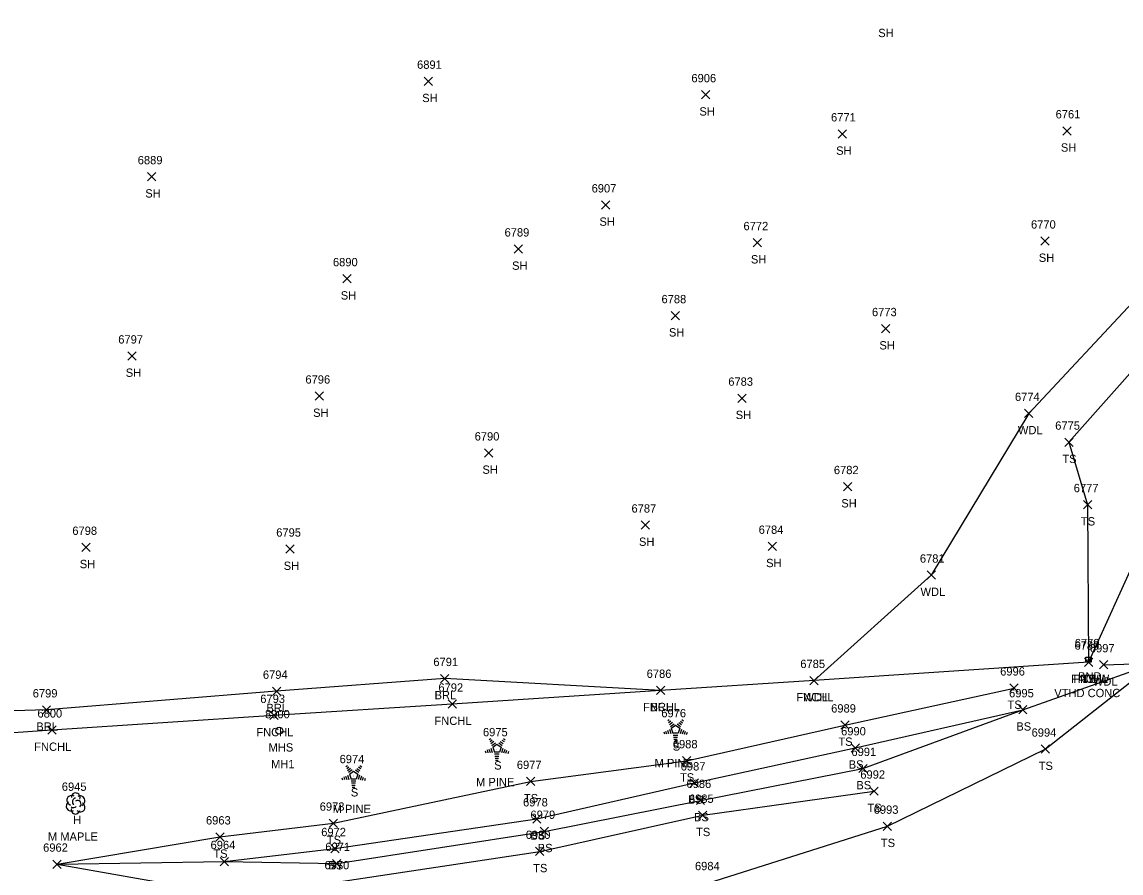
# Model space of a CAD drawing. Extents: x 1678863 to 1683592, y 407783 to 418211.
# Drawn here: x 1680572.7 to 1680837, y 408997.5 to 409202.1 of the extents above; entities that cross this region are included whole.
import ezdxf

# ---------------------------------------------------------------- set-up
doc = ezdxf.new("R2010")
doc.units = 0
for name, color, linetype in [('L_A', 7, 'Continuous'), ('L_C', 7, 'Continuous'), ('L_I', 7, 'Continuous'), ('L_TIC', 7, 'Continuous'), ('LABL', 7, 'Continuous'), ('LAWA', 7, 'Continuous'), ('LELB', 7, 'Continuous'), ('Level 18', 7, 'Continuous'), ('LFNC', 7, 'Continuous'), ('LTC', 7, 'Continuous'), ('LTD', 7, 'Continuous'), ('M_A', 7, 'Continuous'), ('M_C', 7, 'Continuous'), ('M_I', 7, 'Continuous'), ('U_A', 7, 'Continuous'), ('U_C', 7, 'Continuous'), ('U_I', 7, 'Continuous'), ('USMH', 7, 'Continuous')]:
    doc.layers.add(name, color=color, linetype=linetype)

msp = doc.modelspace()

# ---------------------------------------------------------------- linework, layer by layer
at = {"layer": 'L_TIC'}
for points in [[(1680669.47, 409186.88), (1680671.47, 409188.88)], [(1680671.47, 409186.88), (1680669.47, 409188.88)], [(1680736.15, 409183.64), (1680738.15, 409185.64)], [(1680738.15, 409183.64), (1680736.15, 409185.64)], [(1680823.09, 409174.96), (1680825.09, 409176.96)], [(1680825.09, 409174.96), (1680823.09, 409176.96)], [(1680769.04, 409174.22), (1680771.04, 409176.22)], [(1680771.04, 409174.22), (1680769.04, 409176.22)], [(1680602.86, 409163.93), (1680604.86, 409165.93)], [(1680604.86, 409163.93), (1680602.86, 409165.93)], [(1680712.1, 409157.15), (1680714.1, 409159.15)], [(1680714.1, 409157.15), (1680712.1, 409159.15)], [(1680691.08, 409146.56), (1680693.08, 409148.56)], [(1680693.08, 409146.56), (1680691.08, 409148.56)], [(1680748.55, 409148.08), (1680750.55, 409150.08)], [(1680750.55, 409148.08), (1680748.55, 409150.08)], [(1680817.79, 409148.47), (1680819.79, 409150.47)], [(1680819.79, 409148.47), (1680817.79, 409150.47)], [(1680649.88, 409139.41), (1680651.88, 409141.41)], [(1680651.88, 409139.41), (1680649.88, 409141.41)], [(1680728.82, 409130.52), (1680730.82, 409132.52)], [(1680730.82, 409130.52), (1680728.82, 409132.52)], [(1680779.44, 409127.41), (1680781.44, 409129.41)], [(1680781.44, 409127.41), (1680779.44, 409129.41)], [(1680598.16, 409120.83), (1680600.16, 409122.83)], [(1680600.16, 409120.83), (1680598.16, 409122.83)], [(1680643.23, 409111.2), (1680645.23, 409113.2)], [(1680645.23, 409111.2), (1680643.23, 409113.2)], [(1680744.89, 409110.68), (1680746.89, 409112.68)], [(1680746.89, 409110.68), (1680744.89, 409112.68)], [(1680813.84, 409107.02), (1680815.84, 409109.02)], [(1680815.84, 409107.02), (1680813.84, 409109.02)], [(1680823.53, 409100.11), (1680825.53, 409102.11)], [(1680825.53, 409100.11), (1680823.53, 409102.11)], [(1680683.96, 409097.52), (1680685.96, 409099.52)], [(1680685.96, 409097.52), (1680683.96, 409099.52)], [(1680770.28, 409089.43), (1680772.28, 409091.43)], [(1680772.28, 409089.43), (1680770.28, 409091.43)], [(1680827.99, 409085.09), (1680829.99, 409087.09)], [(1680829.99, 409085.09), (1680827.99, 409087.09)], [(1680721.61, 409080.19), (1680723.61, 409082.19)], [(1680723.61, 409080.19), (1680721.61, 409082.19)], [(1680587.1, 409074.83), (1680589.1, 409076.83)], [(1680589.1, 409074.83), (1680587.1, 409076.83)], [(1680752.2, 409075.08), (1680754.2, 409077.08)], [(1680754.2, 409075.08), (1680752.2, 409077.08)], [(1680636.15, 409074.41), (1680638.15, 409076.41)], [(1680638.15, 409074.41), (1680636.15, 409076.41)], [(1680790.41, 409068.15), (1680792.41, 409070.15)], [(1680792.41, 409068.15), (1680790.41, 409070.15)], [(1680828.25, 409047.23), (1680830.25, 409049.23)], [(1680830.25, 409047.23), (1680828.25, 409049.23)], [(1680828.25, 409047.23), (1680830.25, 409049.23)], [(1680830.25, 409047.23), (1680828.25, 409049.23)], [(1680828.25, 409047.23), (1680830.25, 409049.23)], [(1680830.25, 409047.23), (1680828.25, 409049.23)], [(1680831.86, 409046.6), (1680833.86, 409048.6)], [(1680833.86, 409046.6), (1680831.86, 409048.6)], [(1680673.38, 409043.29), (1680675.38, 409045.29)], [(1680675.38, 409043.29), (1680673.38, 409045.29)], [(1680762.22, 409042.82), (1680764.22, 409044.82)], [(1680764.22, 409042.82), (1680762.22, 409044.82)], [(1680762.22, 409042.82), (1680764.22, 409044.82)], [(1680764.22, 409042.82), (1680762.22, 409044.82)], [(1680632.95, 409040.23), (1680634.95, 409042.23)], [(1680634.95, 409040.23), (1680632.95, 409042.23)], [(1680725.31, 409040.45), (1680727.31, 409042.45)], [(1680727.31, 409040.45), (1680725.31, 409042.45)], [(1680725.31, 409040.45), (1680727.31, 409042.45)], [(1680727.31, 409040.45), (1680725.31, 409042.45)], [(1680810.34, 409041.01), (1680812.34, 409043.01)], [(1680812.34, 409041.01), (1680810.34, 409043.01)], [(1680577.59, 409035.75), (1680579.59, 409037.75)], [(1680579.59, 409035.75), (1680577.59, 409037.75)], [(1680675.17, 409037.14), (1680677.17, 409039.14)], [(1680677.17, 409037.14), (1680675.17, 409039.14)], [(1680812.43, 409035.78), (1680814.43, 409037.78)], [(1680814.43, 409035.78), (1680812.43, 409037.78)], [(1680812.43, 409035.78), (1680814.43, 409037.78)], [(1680814.43, 409035.78), (1680812.43, 409037.78)], [(1680632.31, 409034.42), (1680634.31, 409036.42)], [(1680634.31, 409034.42), (1680632.31, 409036.42)], [(1680578.88, 409030.91), (1680580.88, 409032.91)], [(1680580.88, 409030.91), (1680578.88, 409032.91)], [(1680769.65, 409032.12), (1680771.65, 409034.12)], [(1680771.65, 409032.12), (1680769.65, 409034.12)], [(1680772.11, 409026.63), (1680774.11, 409028.63)], [(1680774.11, 409026.63), (1680772.11, 409028.63)], [(1680817.84, 409026.32), (1680819.84, 409028.32)], [(1680819.84, 409026.32), (1680817.84, 409028.32)], [(1680731.55, 409023.53), (1680733.55, 409025.53)], [(1680733.55, 409023.53), (1680731.55, 409025.53)], [(1680773.95, 409021.67), (1680775.95, 409023.67)], [(1680775.95, 409021.67), (1680773.95, 409023.67)], [(1680694.02, 409018.55), (1680696.02, 409020.55)], [(1680696.02, 409018.55), (1680694.02, 409020.55)], [(1680733.45, 409018.19), (1680735.45, 409020.19)], [(1680735.45, 409018.19), (1680733.45, 409020.19)], [(1680734.9, 409013.98), (1680736.9, 409015.98)], [(1680736.9, 409013.98), (1680734.9, 409015.98)], [(1680776.65, 409016.22), (1680778.65, 409018.22)], [(1680778.65, 409016.22), (1680776.65, 409018.22)], [(1680646.61, 409008.52), (1680648.61, 409010.52)], [(1680648.61, 409008.52), (1680646.61, 409010.52)], [(1680695.53, 409009.55), (1680697.53, 409011.55)], [(1680697.53, 409009.55), (1680695.53, 409011.55)], [(1680735.42, 409010.41), (1680737.42, 409012.41)], [(1680737.42, 409010.41), (1680735.42, 409012.41)], [(1680697.31, 409006.55), (1680699.31, 409008.55)], [(1680699.31, 409006.55), (1680697.31, 409008.55)], [(1680779.87, 409007.78), (1680781.87, 409009.78)], [(1680781.87, 409007.78), (1680779.87, 409009.78)], [(1680619.3, 409005.21), (1680621.3, 409007.21)], [(1680621.3, 409005.21), (1680619.3, 409007.21)], [(1680646.98, 409002.4), (1680648.98, 409004.4)], [(1680648.98, 409002.4), (1680646.98, 409004.4)], [(1680696.24, 409001.73), (1680698.24, 409003.73)], [(1680698.24, 409001.73), (1680696.24, 409003.73)], [(1680580.13, 408998.66), (1680582.13, 409000.66)], [(1680582.13, 408998.66), (1680580.13, 409000.66)], [(1680580.13, 408998.66), (1680582.13, 409000.66)], [(1680582.13, 408998.66), (1680580.13, 409000.66)], [(1680580.13, 408998.66), (1680582.13, 409000.66)], [(1680582.13, 408998.66), (1680580.13, 409000.66)], [(1680620.4, 408999.29), (1680622.4, 409001.29)], [(1680622.4, 408999.29), (1680620.4, 409001.29)], [(1680620.4, 408999.29), (1680622.4, 409001.29)], [(1680622.4, 408999.29), (1680620.4, 409001.29)], [(1680647.39, 408998.82), (1680649.39, 409000.82)], [(1680649.39, 408998.82), (1680647.39, 409000.82)]]:
    msp.add_lwpolyline(points, dxfattribs=at)
at = {"layer": 'LABL'}
msp.add_lwpolyline([(1680726.31, 409041.45), (1680674.38, 409044.29), (1680633.95, 409041.23), (1680578.59, 409036.75), (1680531.3, 409035.36), (1680498.96, 409035.63)], dxfattribs=at)
at = {"layer": 'LAWA'}
for points in [[(1680896.75, 409201.77), (1680859.26, 409167.08), (1680840.94, 409135.88), (1680814.84, 409108.02), (1680791.41, 409069.15), (1680763.22, 409043.82)], [(1680832.86, 409047.6), (1680845.07, 409047.96), (1680857.13, 409068.65), (1680880.59, 409112.63), (1680897.26, 409128.4), (1680910.16, 409137.35), (1680926.51, 409159.25), (1680914.95, 409173.01)]]:
    msp.add_lwpolyline(points, dxfattribs=at)
at = {"layer": 'LELB'}
for points in [[(1680883.78, 409168.4), (1680867.18, 409158.31), (1680851.39, 409131.33), (1680824.53, 409101.11), (1680828.99, 409086.09), (1680829.25, 409048.23)], [(1680581.13, 408999.66), (1680621.4, 409000.29), (1680647.98, 409003.4), (1680696.53, 409010.55), (1680734.45, 409019.19), (1680773.11, 409027.63), (1680813.43, 409036.78), (1680845.07, 409047.96)], [(1680622.09, 408948.51), (1680651.12, 408965.11), (1680694.79, 408980.06), (1680737.87, 408995.22), (1680780.87, 409008.78), (1680818.84, 409027.32), (1680845.07, 409047.96)], [(1680581.13, 408999.66), (1680620.3, 409006.21), (1680647.61, 409009.52), (1680695.02, 409019.55), (1680732.55, 409024.53), (1680770.65, 409033.12), (1680811.34, 409042.01)], [(1680621.4, 409000.29), (1680648.39, 408999.82), (1680698.31, 409007.55), (1680735.9, 409014.98), (1680774.95, 409022.67), (1680813.43, 409036.78)], [(1680581.13, 408999.66), (1680622.52, 408992.36), (1680648.86, 408995.44), (1680697.24, 409002.73), (1680736.42, 409011.41), (1680777.65, 409017.22)]]:
    msp.add_lwpolyline(points, dxfattribs=at)
at = {"layer": 'Level 18'}
msp.add_lwpolyline([(1680828.6, 409049.45), (1680829.85, 409049.45), (1680829.85, 409048.2), (1680828.6, 409048.2)], close=True, dxfattribs=at)
msp.add_circle((1680829.22, 409048.82), 0.0833, dxfattribs=at)
at = {"layer": 'LFNC'}
for points in [[(1681020.97, 409571.46), (1681000.88, 409509.71), (1680983.07, 409456.41), (1680966.99, 409407.97), (1680949.18, 409354.43), (1680932.44, 409305.73), (1680912.74, 409247.22), (1680896.75, 409201.77), (1680883.78, 409168.4), (1680880.32, 409157.8), (1680862.92, 409120.89), (1680841.17, 409074.48), (1680829.25, 409048.23)], [(1680829.25, 409048.23), (1680763.22, 409043.82), (1680726.31, 409041.45), (1680676.17, 409038.14), (1680633.31, 409035.42), (1680579.88, 409031.91), (1680532.48, 409028.57), (1680500, 409026.54), (1680429.19, 409022.26), (1680381.9, 409017.89)]]:
    msp.add_lwpolyline(points, dxfattribs=at)
at = {"layer": 'LTC'}
for p, q in [((1680728.03, 409034.19), (1680728.38, 409034.44)), ((1680731.42, 409034.43), (1680731.84, 409034.12)), ((1680727.51, 409031.68), (1680727.73, 409031.03)), ((1680727.97, 409031.9), (1680728.24, 409031.06)), ((1680728.24, 409033.72), (1680728.76, 409034.1)), ((1680728.42, 409032.11), (1680728.76, 409031.09)), ((1680728.45, 409033.25), (1680729.15, 409033.77)), ((1680728.65, 409032.79), (1680729.53, 409033.43)), ((1680728.88, 409032.33), (1680729.89, 409033.07)), ((1680728.88, 409032.33), (1680729.27, 409031.14)), ((1680729.89, 409033.07), (1680730.89, 409032.34)), ((1680730.31, 409033.38), (1680731.12, 409032.79)), ((1680730.89, 409032.34), (1680730.5, 409031.14)), ((1680730.68, 409033.73), (1680731.36, 409033.24)), ((1680731.33, 409032.07), (1680730.99, 409031.03)), ((1680731.05, 409034.08), (1680731.6, 409033.68)), ((1680731.77, 409031.82), (1680731.48, 409030.94)), ((1680732.21, 409031.57), (1680731.98, 409030.84)), ((1680685.08, 409029.63), (1680685.43, 409029.88)), ((1680685.29, 409029.16), (1680685.82, 409029.54)), ((1680685.5, 409028.69), (1680686.2, 409029.21)), ((1680687.73, 409029.17), (1680688.41, 409028.68)), ((1680688.1, 409029.52), (1680688.65, 409029.12)), ((1680688.48, 409029.87), (1680688.89, 409029.56)), ((1680727.06, 409031.46), (1680727.21, 409031)), ((1680730.5, 409031.14), (1680729.27, 409031.14)), ((1680730.46, 409030.64), (1680729.31, 409030.64)), ((1680730.37, 409030.14), (1680729.39, 409030.14)), ((1680730.29, 409029.64), (1680729.46, 409029.64)), ((1680730.21, 409029.14), (1680729.53, 409029.14)), ((1680732.66, 409031.32), (1680732.47, 409030.75)), ((1680684.11, 409026.9), (1680684.26, 409026.44)), ((1680684.56, 409027.12), (1680684.78, 409026.47)), ((1680685.02, 409027.34), (1680685.29, 409026.5)), ((1680685.48, 409027.55), (1680685.81, 409026.54)), ((1680685.71, 409028.23), (1680686.58, 409028.87)), ((1680685.93, 409027.77), (1680686.94, 409028.51)), ((1680685.93, 409027.77), (1680686.32, 409026.58)), ((1680687.55, 409026.58), (1680686.32, 409026.58)), ((1680686.94, 409028.51), (1680687.94, 409027.78)), ((1680687.36, 409028.82), (1680688.17, 409028.23)), ((1680687.94, 409027.78), (1680687.55, 409026.58)), ((1680688.38, 409027.51), (1680688.04, 409026.47)), ((1680688.82, 409027.26), (1680688.53, 409026.38)), ((1680689.27, 409027.01), (1680689.03, 409026.28)), ((1680689.71, 409026.76), (1680689.52, 409026.19)), ((1680687.51, 409026.08), (1680686.36, 409026.08)), ((1680687.43, 409025.58), (1680686.44, 409025.58)), ((1680687.34, 409025.08), (1680686.51, 409025.08)), ((1680687.26, 409024.58), (1680686.58, 409024.58)), ((1680650.59, 409023.15), (1680650.95, 409023.41)), ((1680650.8, 409022.69), (1680651.33, 409023.07)), ((1680650.99, 409021.08), (1680651.32, 409020.06)), ((1680651.01, 409022.22), (1680651.72, 409022.73)), ((1680651.22, 409021.75), (1680652.1, 409022.39)), ((1680651.45, 409021.3), (1680652.46, 409022.03)), ((1680651.45, 409021.3), (1680651.84, 409020.11)), ((1680652.46, 409022.03), (1680653.46, 409021.31)), ((1680652.88, 409022.35), (1680653.69, 409021.76)), ((1680653.46, 409021.31), (1680653.07, 409020.11)), ((1680653.25, 409022.69), (1680653.93, 409022.2)), ((1680653.89, 409021.04), (1680653.56, 409020)), ((1680653.62, 409023.04), (1680654.17, 409022.64)), ((1680653.99, 409023.39), (1680654.41, 409023.09)), ((1680649.63, 409020.43), (1680649.78, 409019.96)), ((1680650.08, 409020.65), (1680650.29, 409019.99)), ((1680650.54, 409020.86), (1680650.81, 409020.03)), ((1680653.07, 409020.11), (1680651.84, 409020.11)), ((1680653.03, 409019.61), (1680651.88, 409019.61)), ((1680652.94, 409019.11), (1680651.96, 409019.11)), ((1680652.86, 409018.61), (1680652.03, 409018.61)), ((1680654.34, 409020.79), (1680654.05, 409019.9)), ((1680654.78, 409020.54), (1680654.55, 409019.81)), ((1680655.23, 409020.29), (1680655.04, 409019.71)), ((1680652.78, 409018.11), (1680652.1, 409018.11))]:
    msp.add_line(p, q, dxfattribs=at)
at = {"layer": 'LTD'}
msp.add_line((1680585.57, 409014.3), (1680585.57, 409014.3), dxfattribs=at)
msp.add_line((1680585.57, 409014.3), (1680585.57, 409014.3), dxfattribs=at)
msp.add_arc((1680585.62, 409015.74), 1.05, 335.5272, 180.9563, dxfattribs=at)
for centre, major_axis, ratio, start_param, end_param in [((1680584.78, 409014.97), (1.21, -0.51), 0.895232, 1.570796, 4.712389), ((1680586.61, 409014.89), (-1.14, -0.48), 0.949671, 1.570796, 4.712389), ((1680584.49, 409013.59), (0.58, -1.04), 0.959034, 3.141593, 6.283185), ((1680585.57, 409012.8), (0.26, 1.06), 0.942809, 1.570796, 4.712389), ((1680585.11, 409013.55), (-0.625, -0.083), 0.423636, 0, 3.141593), ((1680585.36, 409014.76), (-0.208, -0.792), 0.645439, 3.141593, 6.283185), ((1680586.07, 409014.14), (-0.5, 0.667), 0.989748, 3.141593, 6.283185), ((1680586.57, 409013.47), (-1.09, 0.79), 0.841452, 1.570796, 4.712389)]:
    msp.add_ellipse(centre, major_axis=major_axis, ratio=ratio, start_param=start_param, end_param=end_param, dxfattribs=at)
at = {"layer": 'USMH'}
for p, q in [((1680634.58, 409031.74), (1680634.58, 409031.74)), ((1680635.42, 409031.74), (1680635.42, 409031.74))]:
    msp.add_line(p, q, dxfattribs=at)
msp.add_circle((1680634.58, 409031.74), 0.833, dxfattribs=at)

# ---------------------------------------------------------------- texts
at = {"layer": 'L_A'}
for s, p in [('SH', (1680778.66, 409198.5)), ('SH', (1680668.96, 409182.88)), ('SH', (1680735.64, 409179.64)), ('SH', (1680768.52, 409170.22)), ('SH', (1680822.58, 409170.96)), ('SH', (1680602.35, 409159.93)), ('SH', (1680711.59, 409153.15)), ('SH', (1680748.03, 409144.08)), ('SH', (1680817.28, 409144.47)), ('SH', (1680690.57, 409142.56)), ('SH', (1680649.37, 409135.41)), ('SH', (1680728.31, 409126.52)), ('SH', (1680778.93, 409123.41)), ('SH', (1680597.65, 409116.83)), ('SH', (1680642.72, 409107.2)), ('SH', (1680744.37, 409106.68)), ('WDL', (1680812.25, 409103.02)), ('TS', (1680822.94, 409096.11)), ('SH', (1680683.45, 409093.52)), ('SH', (1680769.77, 409085.43)), ('TS', (1680827.4, 409081.09)), ('SH', (1680721.1, 409076.19)), ('SH', (1680586.59, 409070.83)), ('SH', (1680635.64, 409070.41)), ('SH', (1680751.68, 409071.08)), ('WDL', (1680788.82, 409064.15)), ('FNCHL', (1680825, 409043.23)), ('FNWW', (1680825.6, 409043.23)), ('TS', (1680827.66, 409043.23)), ('WDL', (1680830.28, 409042.6)), ('BRL', (1680671.93, 409039.29)), ('FNCHL', (1680758.97, 409038.82)), ('WDL', (1680760.64, 409038.82)), ('BRL', (1680631.49, 409036.23)), ('FNCHL', (1680722.06, 409036.45)), ('BRL', (1680723.86, 409036.45)), ('TS', (1680809.75, 409037.01)), ('FNCHL', (1680671.91, 409033.14)), ('BRL', (1680576.13, 409031.75)), ('FNCHL', (1680629.06, 409030.42)), ('BS', (1680811.87, 409031.78)), ('BS', (1680811.87, 409031.78)), ('FNCHL', (1680575.63, 409026.91)), ('S', (1680729.22, 409026.98)), ('TS', (1680769.06, 409028.12)), ('S', (1680686.27, 409022.42)), ('BS', (1680771.55, 409022.63)), ('TS', (1680817.25, 409022.32)), ('TS', (1680730.96, 409019.53)), ('BS', (1680773.39, 409017.67)), ('S', (1680651.79, 409015.94)), ('TS', (1680693.43, 409014.55)), ('BS', (1680732.89, 409014.19)), ('TS', (1680776.06, 409012.22)), ('H', (1680585.01, 409009.3)), ('BS', (1680734.34, 409009.98)), ('TS', (1680734.83, 409006.41)), ('TS', (1680646.02, 409004.52)), ('BS', (1680694.97, 409005.55)), ('TS', (1680779.28, 409003.78)), ('TS', (1680618.71, 409001.21)), ('BS', (1680696.76, 409002.55)), ('BS', (1680646.42, 408998.4)), ('TS', (1680695.65, 408997.73))]:
    msp.add_text(s, height=2, dxfattribs=at).set_placement(p)
at = {"layer": 'L_C'}
for s, p in [('M PINE', (1680724.85, 409022.98)), ('M PINE', (1680681.91, 409018.42)), ('M PINE', (1680647.42, 409011.94)), ('M MAPLE', (1680578.93, 409005.3))]:
    msp.add_text(s, height=2, dxfattribs=at).set_placement(p)
at = {"layer": 'L_I'}
for s, p in [('6891', (1680667.73, 409190.88)), ('6906', (1680733.71, 409187.64)), ('6771', (1680767.3, 409178.22)), ('6761', (1680821.31, 409178.96)), ('6889', (1680600.54, 409167.93)), ('6907', (1680709.71, 409161.15)), ('6772', (1680746.24, 409152.08)), ('6770', (1680815.4, 409152.47)), ('6789', (1680688.77, 409150.56)), ('6890', (1680647.49, 409143.41)), ('6788', (1680726.52, 409134.52)), ('6773', (1680777.14, 409131.41)), ('6797', (1680595.85, 409124.83)), ('6796', (1680640.87, 409115.2)), ('6783', (1680742.58, 409114.68)), ('6774', (1680811.53, 409111.02)), ('6775', (1680821.22, 409104.11)), ('6790', (1680681.57, 409101.52)), ('6782', (1680767.98, 409093.43)), ('6777', (1680825.68, 409089.09)), ('6787', (1680719.3, 409084.19)), ('6798', (1680584.8, 409078.83)), ('6795', (1680633.85, 409078.41)), ('6784', (1680749.89, 409079.08)), ('6781', (1680788.67, 409072.15)), ('6780', (1680825.86, 409051.23)), ('6780', (1680825.86, 409051.23)), ('6780', (1680825.86, 409051.23)), ('6997', (1680829.55, 409050.6)), ('6791', (1680671.64, 409047.29)), ('6785', (1680759.91, 409046.82)), ('6785', (1680759.91, 409046.82)), ('6794', (1680630.64, 409044.23)), ('6786', (1680722.95, 409044.45)), ('6786', (1680722.95, 409044.45)), ('6996', (1680807.98, 409045.01)), ('6792', (1680672.86, 409041.14)), ('6799', (1680575.28, 409039.75)), ('6793', (1680630.01, 409038.42)), ('6995', (1680810.12, 409039.78)), ('6995', (1680810.12, 409039.78)), ('6800', (1680576.41, 409034.91)), ('6976', (1680726.47, 409034.98)), ('6989', (1680767.33, 409036.12)), ('6975', (1680683.57, 409030.42)), ('6990', (1680769.72, 409030.63)), ('6994', (1680815.54, 409030.32)), ('6988', (1680729.24, 409027.53)), ('6991', (1680772.21, 409025.67)), ('6974', (1680649.09, 409023.94)), ('6977', (1680691.72, 409022.55)), ('6987', (1680731.14, 409022.19)), ('6992', (1680774.34, 409020.22)), ('6945', (1680582.27, 409017.3)), ('6986', (1680732.53, 409017.98)), ('6985', (1680733.11, 409014.41)), ('6973', (1680644.31, 409012.52)), ('6978', (1680693.22, 409013.55)), ('6993', (1680777.56, 409011.78)), ('6963', (1680616.95, 409009.21)), ('6979', (1680695, 409010.55)), ('6972', (1680644.67, 409006.4)), ('6980', (1680693.85, 409005.73)), ('6964', (1680618.05, 409003.29)), ('6964', (1680618.05, 409003.29)), ('6962', (1680577.78, 409002.66)), ('6962', (1680577.78, 409002.66)), ('6962', (1680577.78, 409002.66)), ('6971', (1680645.65, 409002.82)), ('6970', (1680645.46, 408998.44)), ('6984', (1680734.57, 408998.22))]:
    msp.add_text(s, height=2, dxfattribs=at).set_placement(p)
at = {"layer": 'LTC'}
for p in [(1680729.77, 409032.08), (1680686.82, 409027.52), (1680652.34, 409021.05)]:
    msp.add_text('.', height=1.04, rotation=270, dxfattribs=at).set_placement(p)
at = {"layer": 'M_A'}
msp.add_text('BND', height=2, dxfattribs=at).set_placement((1680826.71, 409043.82))
at = {"layer": 'M_C'}
msp.add_text('VTHD CONC', height=2, dxfattribs=at).set_placement((1680820.99, 409039.82))
at = {"layer": 'M_I'}
msp.add_text('6779', height=2, dxfattribs=at).set_placement((1680825.91, 409051.82))
at = {"layer": 'U_A'}
msp.add_text('MHS', height=2, dxfattribs=at).set_placement((1680632, 409026.74))
at = {"layer": 'U_C'}
msp.add_text('MH1', height=2, dxfattribs=at).set_placement((1680632.61, 409022.74))
at = {"layer": 'U_I'}
msp.add_text('8900', height=2, dxfattribs=at).set_placement((1680631.16, 409034.74))

doc.saveas('drawing.dxf')
